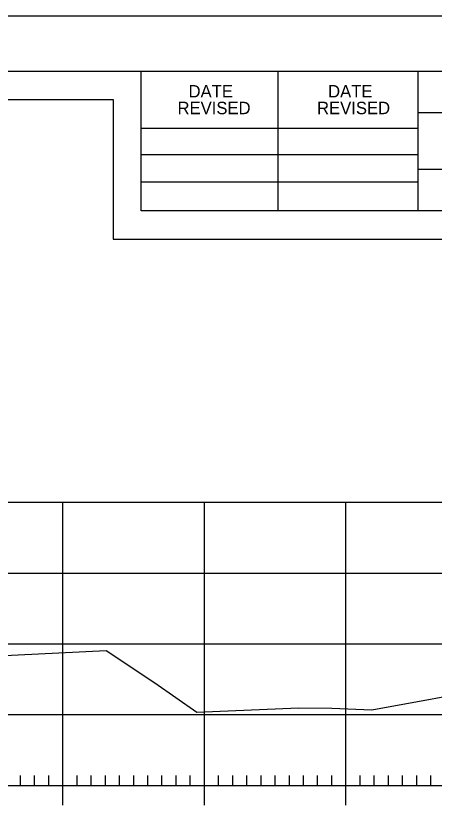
# Model space of a CAD drawing. Extents: x 1368910 to 1369601, y 380116 to 380950.
# Drawn here: x 1369524.3 to 1369553.8, y 380680.7 to 380737.1 of the extents above; entities that cross this region are included whole.
import ezdxf

# ---------------------------------------------------------------- set-up
doc = ezdxf.new("R2010")
doc.units = 0
for name, color, linetype in [('R_Axis', 7, 'Continuous'), ('R_Border', 7, 'Continuous'), ('R_Exist Surface', 7, 'Continuous'), ('R_Grid', 7, 'Continuous'), ('R_No Plot', 7, 'Continuous')]:
    doc.layers.add(name, color=color, linetype=linetype)

msp = doc.modelspace()

# ---------------------------------------------------------------- linework, layer by layer
at = {"layer": 'R_Axis'}
for p, q in [((1369527.59, 380681.359), (1369527.59, 380684.159)), ((1369537.59, 380681.359), (1369537.59, 380684.159)), ((1369547.59, 380681.359), (1369547.59, 380684.159)), ((1369524.59, 380682.759), (1369524.59, 380683.459)), ((1369525.59, 380682.759), (1369525.59, 380683.459)), ((1369526.59, 380682.759), (1369526.59, 380683.459)), ((1369528.59, 380682.759), (1369528.59, 380683.459)), ((1369529.59, 380682.759), (1369529.59, 380683.459)), ((1369530.59, 380682.759), (1369530.59, 380683.459)), ((1369531.59, 380682.759), (1369531.59, 380683.459)), ((1369532.59, 380682.759), (1369532.59, 380683.459)), ((1369533.59, 380682.759), (1369533.59, 380683.459)), ((1369534.59, 380682.759), (1369534.59, 380683.459)), ((1369535.59, 380682.759), (1369535.59, 380683.459)), ((1369536.59, 380682.759), (1369536.59, 380683.459)), ((1369538.59, 380682.759), (1369538.59, 380683.459)), ((1369539.59, 380682.759), (1369539.59, 380683.459)), ((1369540.59, 380682.759), (1369540.59, 380683.459)), ((1369541.59, 380682.759), (1369541.59, 380683.459)), ((1369542.59, 380682.759), (1369542.59, 380683.459)), ((1369543.59, 380682.759), (1369543.59, 380683.459)), ((1369544.59, 380682.759), (1369544.59, 380683.459)), ((1369545.59, 380682.759), (1369545.59, 380683.459)), ((1369546.59, 380682.759), (1369546.59, 380683.459)), ((1369548.59, 380682.759), (1369548.59, 380683.459)), ((1369549.59, 380682.759), (1369549.59, 380683.459)), ((1369550.59, 380682.759), (1369550.59, 380683.459)), ((1369551.59, 380682.759), (1369551.59, 380683.459)), ((1369552.59, 380682.759), (1369552.59, 380683.459)), ((1369553.59, 380682.759), (1369553.59, 380683.459)), ((1369297.59, 380682.759), (1369577.59, 380682.759))]:
    msp.add_line(p, q, dxfattribs=at)
at = {"layer": 'R_Border'}
for p, q in [((1369279.59, 380733.219), (1369595.77, 380733.219)), ((1369533.13, 380723.339), (1369533.13, 380733.219)), ((1369542.81, 380723.339), (1369542.81, 380733.219)), ((1369552.67, 380733.219), (1369552.67, 380723.339)), ((1369595.77, 380730.279), (1369552.67, 380730.279)), ((1369533.13, 380729.199), (1369552.67, 380729.199)), ((1369533.13, 380727.339), (1369552.67, 380727.339)), ((1369595.77, 380726.279), (1369552.67, 380726.279)), ((1369533.13, 380725.399), (1369552.67, 380725.399)), ((1369595.77, 380723.339), (1369533.13, 380723.339))]:
    msp.add_line(p, q, dxfattribs=at)
at = {"layer": 'R_Exist Surface'}
msp.add_lwpolyline([(1369517.72, 380691.662), (1369530.654, 380692.291), (1369534.092, 380690.01), (1369537.049, 380687.943), (1369544.245, 380688.244), (1369546.58, 380688.221), (1369549.426, 380688.092), (1369558.204, 380689.69), (1369564.489, 380691.792), (1369568.163, 380691.776), (1369569.894, 380691.676), (1369571.144, 380691.841), (1369573.442, 380692.14), (1369577.59, 380692.301)], dxfattribs=at)
at = {"layer": 'R_Grid'}
for p, q in [((1369297.59, 380702.759), (1369577.59, 380702.759)), ((1369527.59, 380682.759), (1369527.59, 380702.759)), ((1369537.59, 380682.759), (1369537.59, 380702.759)), ((1369547.59, 380682.759), (1369547.59, 380702.759)), ((1369297.59, 380697.759), (1369577.59, 380697.759)), ((1369297.59, 380692.759), (1369577.59, 380692.759)), ((1369297.59, 380687.759), (1369577.59, 380687.759)), ((1369297.59, 380682.759), (1369577.59, 380682.759))]:
    msp.add_line(p, q, dxfattribs=at)
at = {"layer": 'R_No Plot'}
for points in [[(1369267.182, 380737.113), (1369600.522, 380737.113), (1369600.522, 380523.776), (1369267.182, 380523.776)], [(1369593.77, 380632.489), (1369281.59, 380632.489), (1369281.59, 380731.219), (1369531.13, 380731.219), (1369531.13, 380721.339), (1369548.67, 380721.339), (1369572.77, 380721.339), (1369572.77, 380699.006), (1369593.77, 380699.006)], [(1369281.59, 380731.219), (1369531.13, 380731.219), (1369531.13, 380721.339), (1369548.67, 380721.339), (1369572.77, 380721.339), (1369572.77, 380699.006), (1369593.77, 380699.006), (1369593.77, 380529.759), (1369281.59, 380529.759)]]:
    msp.add_lwpolyline(points, close=True, dxfattribs=at)

# ---------------------------------------------------------------- texts
at = {"layer": 'R_Border'}
for s, p in [('DATE', (1369536.468, 380731.355)), ('DATE', (1369546.328, 380731.355)), ('REVISED', (1369535.688, 380730.175)), ('REVISED', (1369545.548, 380730.175))]:
    msp.add_text(s, height=0.8792, dxfattribs=at).set_placement(p)

doc.saveas('drawing.dxf')
